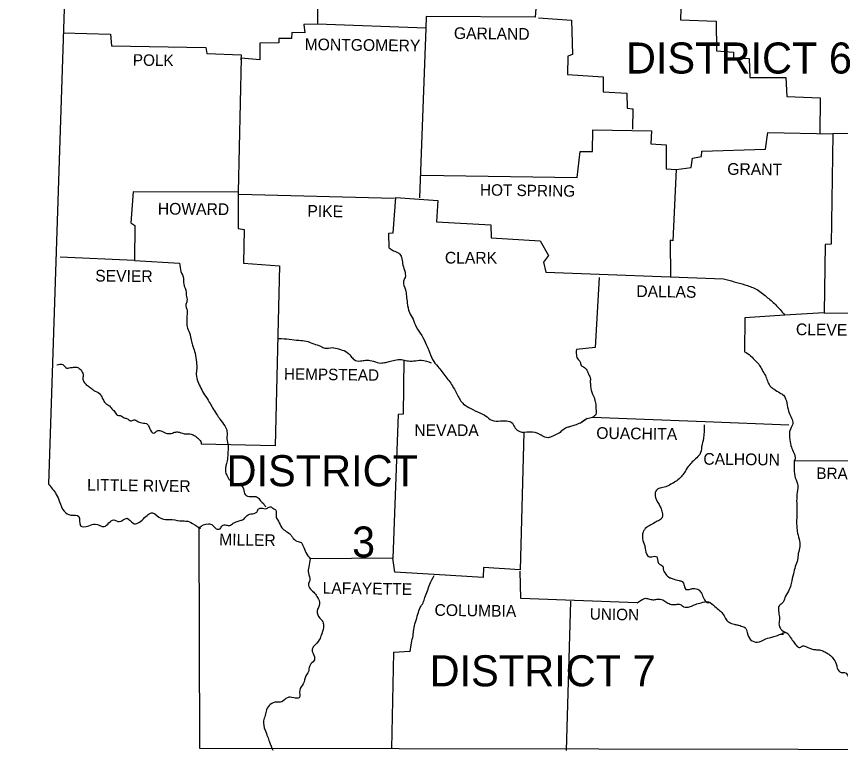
# Model space of a CAD drawing. Extents: x -42408 to 34530, y -43140 to 20491.
# Drawn here: x 1592 to 3107, y -9853 to -8503 of the extents above; entities that cross this region are included whole.
import ezdxf

# ---------------------------------------------------------------- set-up
doc = ezdxf.new("R2010")
doc.units = 0
for name, color, linetype in [('1', 7, 'Continuous'), ('2', 7, 'Continuous'), ('3', 7, 'Continuous')]:
    doc.layers.add(name, color=color, linetype=linetype)

msp = doc.modelspace()

# ---------------------------------------------------------------- linework, layer by layer
at = {"layer": '1'}
for points in [[(1592.1, -7172.4), (1695.7, -8004.5), (1650.7, -9362.9)], [(2146.3, -8224.3), (2145.3, -8517.2), (2120.3, -8517.7), (2122.3, -8532.8), (2098.3, -8532.3), (2097.8, -8543.3), (2074.2, -8543.3), (2074.7, -8551.3), (2039.7, -8552.3), (2039.2, -8582.8), (2005.1, -8579.8), (1999.6, -8826.1), (1806.9, -8825.6), (1802.4, -8882.7), (1809.4, -8887.7), (1808.9, -8951.8), (1672.2, -8945.8)], [(2714.1, -8444.6), (2550.4, -8439.6), (2545.9, -8504.2), (2345.6, -8503.2), (2344.6, -8524.7)], [(2758.6, -8443.1), (2814.7, -8446.6), (2812.7, -8509.2), (2878.3, -8511.7), (2879.3, -8566.3), (2910.3, -8568.8), (2910.3, -8578.3), (2939.4, -8580.3), (2940.4, -8615.4), (3006.5, -8615.4), (3008.5, -8649.9), (3069.6, -8652.9), (3069, -8718)], [(2551.9, -8505.2), (2612.4, -8509.7), (2614.4, -8572.8), (2605.9, -8575.8), (2604.9, -8609.4), (2670.5, -8613.9), (2670.5, -8641.4), (2714.1, -8643.9), (2714.6, -8671.4), (2725.1, -8672.9), (2724.6, -8710)], [(2344.6, -8524.7), (2145.3, -8517.2)], [(2344.6, -8524.7), (2333.1, -8836.7)], [(1678.2, -8532.8), (1764.8, -8535.8), (1766.8, -8556.8), (1940, -8560.3), (1942, -8571.3), (2005.1, -8573.3), (2004.6, -8582.8)], [(3666.3, -8660.4), (3477.1, -8655.4), (3476.1, -8717), (3093.1, -8718.5)], [(2336.6, -8795.1), (2623, -8799.1), (2628.5, -8751.5), (2651, -8751.5), (2651.5, -8711.5), (2759.6, -8713), (2758.6, -8737), (2786.7, -8739), (2786.7, -8783.1), (2804.7, -8784.6)], [(2804.7, -8784.6), (2832.7, -8780.6), (2834.7, -8763.6), (2851.3, -8760.6), (2852.3, -8750.5), (2968.9, -8747), (2973.4, -8716.5), (3093.1, -8718.5)], [(3093.1, -8719.5), (3090.1, -8921.8), (3078.6, -8922.3), (3077.1, -9047.9)], [(2804.7, -8784.6), (2798.7, -8915.8), (2794.2, -8914.3), (2794.7, -8982.4)], [(1999.6, -8826.1), (1999.6, -8892.7), (2010.6, -8894.7), (2009.6, -8956.8), (2075.7, -8961.8), (2067.7, -9292.8), (1931.5, -9289.3)], [(2000.6, -8829.6), (2287, -8837.2)], [(2277.5, -8928.8), (2276.5, -8901.2), (2284.5, -8900.7), (2289.5, -8836.2), (2366.6, -8841.2), (2364.6, -8880.7), (2464.2, -8886.2), (2464.7, -8910.3), (2554.9, -8915.8), (2570.4, -8942.8), (2560.9, -8954.8), (2565.4, -8973.3), (2891.8, -8985.4)], [(1808.9, -8951.8), (1892, -8956.8)], [(2663.5, -8982.9), (2656, -9111.5), (2621.5, -9115.5)], [(3005, -9052.4), (2930.9, -9057), (2930.4, -9119.5)], [(3077.1, -9047.9), (3004, -9052.4)], [(3077.1, -9047.9), (3254.3, -9048.9)], [(2304, -9134.6), (2303, -9234.2), (2294, -9235.2), (2284, -9499)], [(2651, -9240.2), (2858.3, -9247.7), (3012, -9253.7)], [(2524.8, -9268.2), (2518.3, -9520.6), (2450.7, -9516.1), (2450.2, -9534.6), (2360.1, -9529.1)], [(3022, -9320.3), (3248.3, -9319.8)], [(1927.5, -9443.5), (1928.5, -9848.5), (3763.5, -9851.5)], [(2360.1, -9529.1), (2287.5, -9525.1), (2284, -9499), (2132.3, -9500.5)], [(2733.1, -9581.6), (2519.3, -9573.6), (2518.3, -9523.1)], [(2610.4, -9578.1), (2602.4, -9853)], [(2316, -9670.8), (2285, -9672.8), (2281.5, -9849)]]:
    msp.add_lwpolyline(points, dxfattribs=at)
for points in [[(2277.5, -8928.8), (2285.5, -8933.8), (2295, -8938.3), (2300, -8945.8), (2302, -8957.3), (2305.5, -8969.8), (2306.5, -8982.9), (2303.5, -8989.9), (2307.5, -9005.9), (2309, -9016.9), (2310.5, -9029.9), (2314.5, -9047.4), (2321.1, -9059.5), (2327.1, -9074), (2337.1, -9089.5), (2345.6, -9106.5), (2349.6, -9115.5), (2357.1, -9134.1), (2366.6, -9146.6), (2381.6, -9165.6), (2395.2, -9185.1), (2402.7, -9199.6), (2414.2, -9215.7), (2427.2, -9223.7), (2443.7, -9232.2), (2454.2, -9237.2), (2466.2, -9245.7), (2481.8, -9246.7), (2493.3, -9246.7), (2503.8, -9251.2), (2508.8, -9260.2), (2517.8, -9266.2), (2524.8, -9268.2)], [(1892, -8956.8), (1894.5, -8971.8), (1899, -8984.9), (1899.5, -8994.9), (1904, -9009.9), (1904, -9015.4), (1905.5, -9026.4), (1903.5, -9032.4), (1906, -9044.4), (1905.5, -9053.4), (1905.5, -9061), (1906, -9073.5), (1910, -9084.5), (1914, -9101), (1916.5, -9109.5), (1920.5, -9122.5), (1923, -9138.6), (1923.5, -9150.6), (1922.5, -9161.6), (1925.5, -9174.1), (1931, -9186.6), (1938, -9198.6), (1946.6, -9212.2), (1952.6, -9222.7), (1960.1, -9234.2), (1966.1, -9243.7), (1975.1, -9255.7), (1979.1, -9265.7), (1979.1, -9279.7), (1981.1, -9292.8), (1980.6, -9307.3), (1979.6, -9320.3), (1976.1, -9338.3), (1978.6, -9346.8), (1988.1, -9359.4), (1994.1, -9362.9), (2004.6, -9364.9), (2009.6, -9371.9), (2012.6, -9382.4), (2023.2, -9385.9), (2034.7, -9386.9), (2040.2, -9392.9), (2047.7, -9400.9), (2050.2, -9404.9)], [(2891.8, -8985.4), (2930.9, -8996.4), (2950.9, -9003.9), (2970.9, -9018.4), (2987.4, -9032.9), (3004, -9051.4)], [(2074.7, -9095), (2093.7, -9096.5), (2111.3, -9098.5), (2124.8, -9100), (2138.8, -9105), (2151.3, -9109.5), (2159.3, -9113), (2172.9, -9112), (2184.4, -9114.5), (2197.4, -9119), (2206.9, -9127.5), (2212.9, -9134.1), (2224.4, -9136.6), (2233.9, -9135.1), (2245.5, -9136.1), (2258.5, -9140.1), (2269, -9139.6), (2277.5, -9137.6), (2287.5, -9135.1), (2300, -9134.1), (2309.5, -9136.1), (2322.1, -9136.6), (2336.6, -9135.1), (2354.6, -9140.1)], [(2621.5, -9115.5), (2621.5, -9125), (2625, -9134.1), (2628.5, -9138.1), (2630, -9144.6), (2634.5, -9147.6), (2641, -9153.6), (2644.5, -9162.1), (2647, -9167.6), (2647, -9174.6), (2647.5, -9181.6), (2648.5, -9190.1), (2654.5, -9205.1), (2656, -9211.2), (2657, -9216.2), (2657.5, -9224.7), (2657.5, -9234.7), (2651, -9240.2)], [(2930.4, -9119.5), (2941.9, -9127), (2951.4, -9137.1), (2958.4, -9144.6), (2962.9, -9153.1), (2968.9, -9163.1), (2977.4, -9182.1), (2984.9, -9188.6), (2995.5, -9195.1), (3002, -9199.6), (3008.5, -9214.2), (3011.5, -9228.7), (3017, -9241.7), (3019.5, -9251.7), (3015, -9261.7), (3014, -9281.7), (3017, -9295.3), (3021, -9305.3), (3023.5, -9316.8), (3022, -9320.3)], [(1666.2, -9143.6), (1677.2, -9143.1), (1684.7, -9149.6), (1689.2, -9149.1), (1697.2, -9148.1), (1704.7, -9148.6), (1710.2, -9153.1), (1714.7, -9161.1), (1714.2, -9168.6), (1714.7, -9171.6), (1718.2, -9178.1), (1724.3, -9183.1), (1730.8, -9188.1), (1736.8, -9192.1), (1746.8, -9198.6), (1747.8, -9200.6), (1751.8, -9208.7), (1756.8, -9215.2), (1762.8, -9219.2), (1769.3, -9226.2), (1772.3, -9229.2), (1777.3, -9236.2), (1782.8, -9236.7), (1790.3, -9241.2), (1795.9, -9242.7), (1801.9, -9246.7), (1807.9, -9244.7), (1815.4, -9247.7), (1825.4, -9250.7), (1830.9, -9251.7), (1837.4, -9261.2), (1843.9, -9269.2), (1851.9, -9264.7), (1866.9, -9269.2), (1876.5, -9269.7), (1885, -9267.2), (1891.5, -9267.7), (1903.5, -9270.7), (1911, -9270.7), (1919, -9273.7), (1926.5, -9279.7), (1931.5, -9286.3), (1931.5, -9289.3)], [(2628.5, -9250.7), (2641.5, -9242.2), (2651, -9240.2)], [(2641.5, -9242.2), (2628.5, -9250.7), (2618.4, -9254.7), (2610.9, -9257.2), (2603.9, -9259.2), (2594.9, -9265.2), (2587.9, -9270.2), (2578.4, -9274.7), (2569.4, -9277.7), (2558.4, -9274.2), (2552.4, -9270.7), (2545.9, -9268.2), (2524.8, -9268.2)], [(2856.3, -9253.7), (2855.3, -9278.7), (2851.8, -9294.3), (2848.3, -9308.3), (2840.7, -9316.3), (2832.7, -9324.3), (2825.2, -9333.3), (2818.7, -9344.3), (2812.2, -9351.3), (2803.7, -9358.4), (2795.2, -9363.4), (2785.7, -9367.9), (2775.2, -9370.4), (2767.6, -9375.9), (2767.1, -9387.9), (2775.7, -9404.9), (2778.7, -9412.9), (2779.7, -9422.4), (2776.2, -9427.9), (2768.1, -9432.5), (2758.6, -9438), (2750.1, -9443), (2744.1, -9451.5), (2743.1, -9463), (2747.1, -9476.5), (2748.6, -9484.5), (2755.1, -9497), (2760.1, -9496.5), (2769.1, -9497), (2770.2, -9499.5), (2770.7, -9502), (2772.7, -9508.6), (2780.2, -9514.1), (2781.2, -9519.1), (2785.7, -9528.6), (2793.2, -9535.1), (2798.7, -9537.1), (2810.2, -9540.6), (2816.2, -9542.1), (2822.7, -9556.6), (2830.7, -9556.1), (2836.7, -9555.1), (2846.8, -9557.6), (2851.3, -9563.6), (2855.8, -9573.6), (2861.8, -9580.6), (2865.8, -9580.6)], [(3022, -9320.3), (3024, -9351.3), (3028.5, -9366.4), (3027, -9382.4), (3026.5, -9397.9), (3026.5, -9411.9), (3026.5, -9425.4), (3026.5, -9439.5), (3027.5, -9449.5), (3031, -9464), (3032.5, -9477.5), (3029.5, -9490.5), (3028, -9502.5), (3024, -9514.6), (3020.5, -9528.1), (3016.5, -9545.6), (3013, -9557.1), (3006, -9569.1), (3001.5, -9580.1), (2994.5, -9587.2), (2993.4, -9599.2), (2995, -9610.2), (2993.9, -9620.2), (2997.5, -9629.7), (3006.5, -9636.2)], [(1650.7, -9362.9), (1665.2, -9381.9), (1671.2, -9395.4), (1679.7, -9412.9), (1692.2, -9419.9), (1706.7, -9422.4), (1709.7, -9439.5), (1724.8, -9440), (1736.8, -9436.5), (1753.3, -9441), (1770.8, -9428.9), (1780.8, -9432), (1795.4, -9425.9), (1806.4, -9435), (1825.4, -9426.9), (1842.4, -9415.9), (1858.4, -9426.4), (1874, -9427.9), (1892.5, -9430.4), (1907, -9431.4), (1920, -9438), (1929.5, -9444.5), (1927.5, -9443.5)], [(1927.5, -9443.5), (1945.1, -9436), (1952.6, -9438.5), (1959.1, -9445), (1966.6, -9445), (1970.6, -9439), (1978.1, -9438.5), (1984.1, -9439), (1990.6, -9435), (1996.1, -9432.5), (2003.6, -9429.9), (2009.1, -9427.9), (2014.1, -9422.4), (2023.2, -9417.9), (2033.7, -9414.4), (2036.7, -9409.4), (2041.7, -9407.4), (2051.7, -9407.9), (2058.2, -9404.9), (2063.7, -9407.4), (2068.7, -9410.9), (2069.7, -9423.9), (2073.7, -9430.9), (2079.7, -9443.5), (2088.2, -9450), (2096.3, -9456.5), (2099.3, -9460.5), (2107.8, -9468), (2115.3, -9470.5), (2118.8, -9476), (2124.3, -9489), (2132.3, -9500.5)], [(2132.3, -9500.5), (2129.3, -9515.1), (2128.8, -9526.6), (2131.3, -9540.1), (2128.8, -9546.6), (2132.8, -9556.1), (2140.3, -9563.6), (2145.8, -9571.6), (2149.3, -9583.2), (2144.8, -9596.2), (2149.8, -9609.7), (2154.3, -9614.7), (2156.8, -9622.7), (2153.3, -9638.2), (2148.8, -9649.7), (2138.8, -9661.3), (2135.8, -9666.8), (2137.3, -9674.3), (2139.8, -9686.3), (2137.3, -9689.8), (2130.8, -9698.3), (2128.8, -9707.8), (2124.3, -9715.8), (2119.3, -9730.3), (2112.8, -9742.4), (2111.8, -9755.9), (2101.8, -9755.9), (2090.2, -9755.9), (2079.7, -9763.4), (2070.2, -9763.9), (2058.7, -9768.4), (2051.7, -9777.9), (2049.2, -9788.4), (2046.2, -9798.4), (2049.2, -9815.5), (2053.7, -9827.5), (2057.2, -9837), (2063.2, -9852.5)], [(2316, -9670.8), (2318.5, -9654.7), (2321.1, -9642.2), (2322.6, -9630.2), (2325.6, -9616.7), (2330.1, -9602.2), (2334.1, -9590.2), (2339.6, -9581.6), (2343.1, -9571.6), (2347.6, -9559.6), (2352.1, -9547.1), (2360.1, -9531.1)], [(2733.1, -9581.6), (2741.1, -9576.1), (2748.6, -9573.1), (2756.1, -9574.6), (2764.1, -9575.6), (2771.2, -9574.6), (2780.2, -9576.1), (2787.7, -9580.6), (2796.2, -9584.2), (2804.7, -9584.2), (2812.2, -9584.2), (2818.7, -9588.7), (2830.7, -9588.2), (2840.7, -9584.2), (2850.8, -9581.1), (2864.3, -9579.6), (2876.3, -9588.2), (2884.8, -9595.2), (2891.8, -9603.2), (2896.8, -9612.2), (2902.3, -9617.2), (2911.3, -9620.7), (2918.3, -9622.2), (2926.9, -9624.7), (2931.4, -9626.7), (2935.4, -9636.2), (2941.9, -9649.2), (2954.4, -9653.7), (2969.9, -9647.7), (2982.4, -9644.2), (2991.4, -9641.2), (2997, -9639.2), (3002, -9638.7), (3000.5, -9637.7), (3006.5, -9636.2), (3012, -9640.2), (3015.5, -9645.7), (3021.5, -9653.7), (3027, -9660.8), (3032.5, -9663.3), (3038, -9660.3), (3045.5, -9662.8), (3052, -9665.3), (3059.5, -9667.3), (3066, -9667.8), (3074.6, -9669.8), (3081.1, -9673.3), (3087.1, -9676.8), (3093.1, -9683.3), (3099.1, -9693.3), (3101.1, -9701.3), (3108.1, -9709.3), (3114.6, -9709.3), (3124.1, -9722.3), (3127.6, -9727.3), (3135.1, -9736.4), (3140.6, -9736.4), (3151.2, -9738.4)]]:
    msp.add_spline(points, degree=3, dxfattribs=at)

# ---------------------------------------------------------------- texts
at = {"layer": '2'}
for s, height, rotation, p in [('GARLAND', 21.53, 359.3658, (2396.2, -8544.3)), ('MONTGOMERY', 21.53, 359.2944, (2121.8, -8564.8)), ('POLK', 21.02, 359.2152, (1805.9, -8593.3)), ('GRANT', 21.53, 359.4032, (2898.8, -8794.1)), ('HOT SPRING', 21.03, 359.2216, (2444.2, -8832.2)), ('HOWARD', 21.53, 359.5145, (1851.9, -8867.2)), ('PIKE', 21.52, 359.0452, (2126.8, -8871.2)), ('SEVIER', 21.53, 359.4271, (1736.8, -8990.4)), ('DALLAS', 21.52, 359.2462, (2731.6, -9018.9)), ('CLEVELAND', 21.53, 359.3377, (3025, -9089)), ('HEMPSTEAD', 21.02, 359.1885, (2083.7, -9170.6)), ('OUACHITA', 21.53, 359.2043, (2658, -9279.7)), ('CALHOUN', 21.53, 359.3634, (2854.8, -9327.3)), ('BRADLEY', 21.02, 359.1449, (3062.5, -9353.3)), ('LITTLE RIVER', 21.53, 359.1697, (1721.8, -9374.9)), ('MILLER', 21.52, 359.1319, (1964.6, -9475.5)), ('LAFAYETTE', 21.52, 359.1839, (2154.8, -9564.6)), ('COLUMBIA', 21.52, 359.2125, (2360.6, -9605.2)), ('UNION', 21.03, 358.9584, (2646, -9612.2))]:
    msp.add_text(s, height=height, rotation=rotation, dxfattribs=at).set_placement(p)
for s, p in [('CLARK', (2379.7, -8957.4)), ('NEVADA', (2323.6, -9274.7))]:
    msp.add_text(s, height=21.53, dxfattribs=at).set_placement(p)
at = {"layer": '3'}
for s, height, p in [('DISTRICT 6', 57.08, (2712.6, -8607.9)), ('DISTRICT', 57.08, (1978.3, -9366.9)), ('3', 56.6, (2209.2, -9497.6)), ('DISTRICT 7', 57.08, (2351.6, -9734.9))]:
    msp.add_text(s, height=height, dxfattribs=at).set_placement(p)

doc.saveas('drawing.dxf')
